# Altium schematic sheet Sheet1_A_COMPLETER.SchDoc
size A4
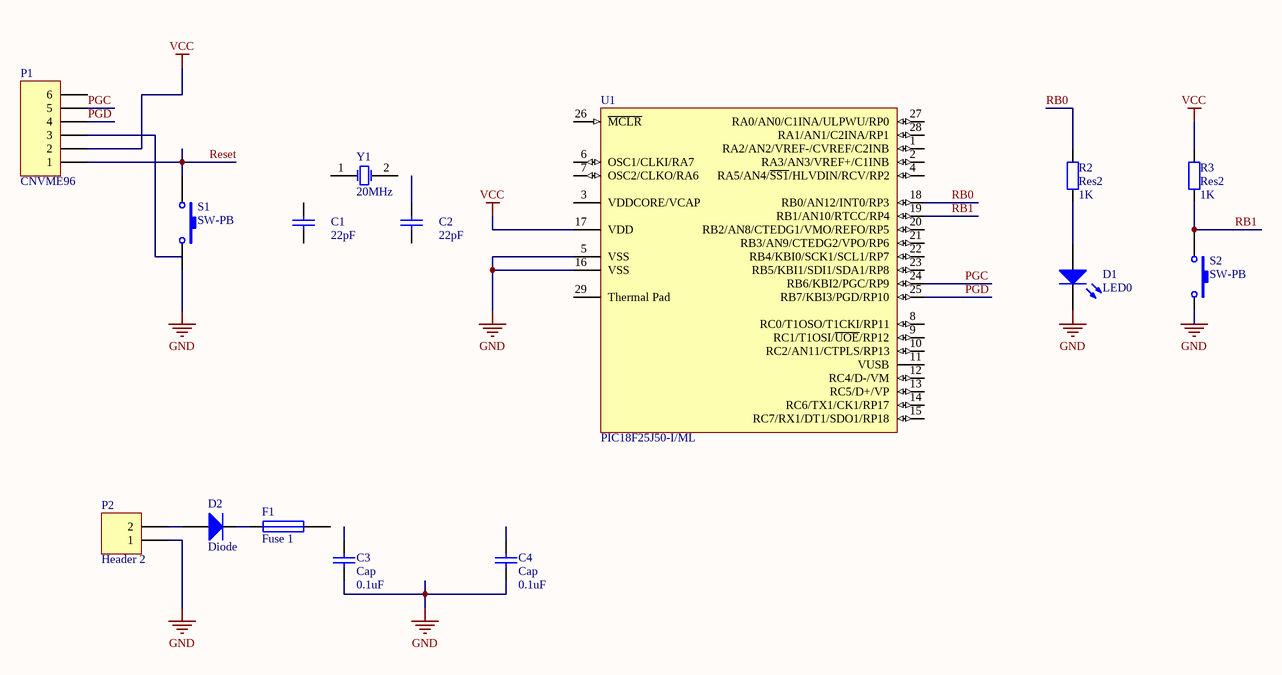
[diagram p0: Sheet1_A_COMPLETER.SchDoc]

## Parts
C1  22pF  [C0805]
C2  22pF  [C0805]
C3  Cap  value 0.1uF  [C1206]
C4  Cap  value 0.1uF  [C1206]
D1  LED0  [3.2X1.6X1.1]
D2  Diode  [SMC]
F1  Fuse 1  [1812]
P1  CNVME96  [HDR1X6]
P2  Header 2  [HDR1X2]
R2  Res2  value 1K  [C1206]
R3  Res2  value 1K  [C1206]
S1  SW-PB  [SW/PB-V4/H7.1]
S2  SW-PB  [SW/PB-V4/H7.1]
U1  PIC18F25J50-I/ML  [SOIC28VWA_L]
Y1  20MHz  [2SMX-3SMXB]

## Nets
GND: C3.2 C4.1 D1.2(K) P2.1 S1.2 S2.2 U1.5(VSS) U1.16(VSS)
VCC: P1.2 R3.2 U1.17(VDD)
PGC: P1.5 U1.24(RB6/KBI2/PGC/RP9)
PGD: P1.4 U1.25(RB7/KBI3/PGD/RP10)
RB0: R2.2 U1.18(RB0/AN12/INT0/RP3)
RB1: R3.1 S2.1 U1.19(RB1/AN10/RTCC/RP4)
Reset: P1.1 S1.1
NetD1_1: D1.1(A) R2.1
NetD2_1: D2.1(A) P2.2
NetD2_2: D2.2(K) F1.1

Not connected (* = marked no-connect by the designer): C1 1 2; C2 1 2; C3 1; C4 2; F1 2; P1 3 6; U1 1(RA2/AN2/VREF-/CVREF/C2INB) 2(RA3/AN3/VREF+/C1INB) 3(VDDCORE/VCAP) 4(RA5/AN4/~{SS1}/HLVDIN/RCV/RP2) 6(OSC1/CLKI/RA7) 7(OSC2/CLKO/RA6) 8(RC0/T1OSO/T1CKI/RP11) 9(RC1/T1OSI/~{UOE}/RP12) 10(RC2/AN11/CTPLS/RP13) 11(VUSB) 12(RC4/D-/VM) 13(RC5/D+/VP) 14(RC6/TX1/CK1/RP17) 15(RC7/RX1/DT1/SDO1/RP18) 20(RB2/AN8/CTEDG1/VMO/REFO/RP5) 21(RB3/AN9/CTEDG2/VPO/RP6) 22(RB4/KBI0/SCK1/SCL1/RP7) 23(RB5/KBI1/SDI1/SDA1/RP8) 26(~{MCLR}) 27(RA0/AN0/C1INA/ULPWU/RP0) 28(RA1/AN1/C2INA/RP1) 29(Thermal_Pad); Y1 1(OSC1) 2(OSC2)

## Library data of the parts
C1-C4 = Cap: Capacitor
D1 = LED0: Typical INFRARED GaAs LED
D2 = Diode: Default Diode
F1 = Fuse 1: Fuse
P1 = Header 6: Header, 6-Pin
P2 = Header 2: Header, 2-Pin
R2 R3 = Res2: Resistor
S1 S2 = SW-PB: Switch
U1 = PIC18F25J50-I/ML: Low Power, High Performance USB Microcontroller with nanoWatt XLP Technology, 28-pin QFN, Industrial Temperature
Y1 = XTAL: Crystal Oscillator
